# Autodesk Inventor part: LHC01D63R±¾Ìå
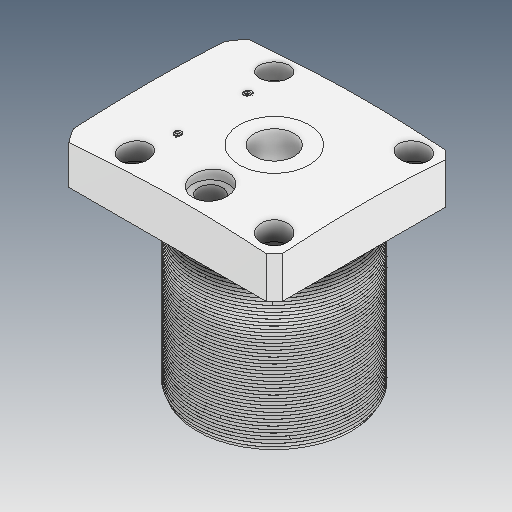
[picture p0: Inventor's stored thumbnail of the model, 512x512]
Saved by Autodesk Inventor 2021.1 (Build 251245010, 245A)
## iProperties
Created: 2021-06
Part Number: LHC01D63R±¾Ìå
Material: Ogólny
Document SubType Name: Modeling
Designer: user
Density: 1 g/cm^3
Appearance: Domyślna
Author: user
Revision Number: ÈÎºÎ
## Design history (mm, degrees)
feature "ÊäÈë1"
feature "ÊäÈë2"
feature "NONE" [ÊäÈë]
node "Bryła1"
node "Bryła2"
node "Bryła3"
